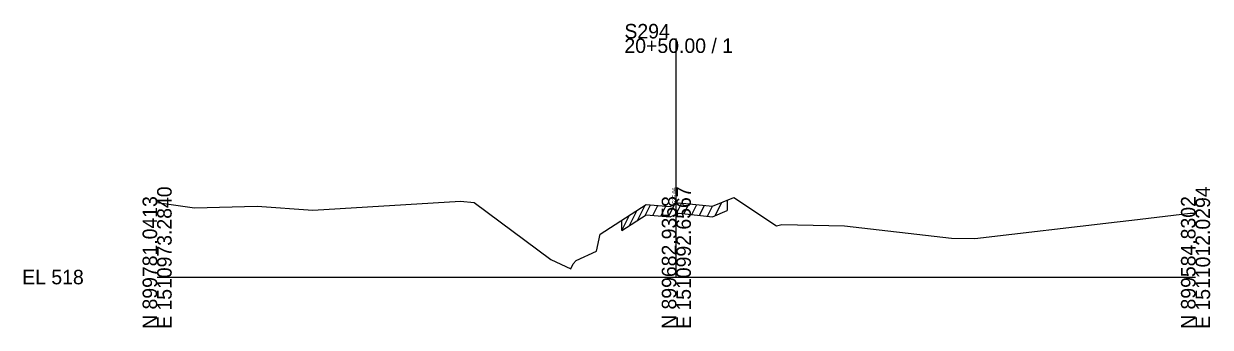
# Model space of a CAD drawing. Extents: x 974 to 2203, y -10 to 19041.
# Drawn here: x 1974.3 to 2202.8, y 990.3 to 1048.9 of the extents above; entities that cross this region are included whole.
import ezdxf

# ---------------------------------------------------------------- set-up
doc = ezdxf.new("R2010")
doc.units = 0
for name, color, linetype in [('RD_GPK_XS_Cell', 7, 'Continuous'), ('RD_XS_ExGround', 7, 'Continuous'), ('RD_XS_ExPaveRet', 7, 'Continuous'), ('RD_XS_TX_Elev_EX', 7, 'Continuous')]:
    doc.layers.add(name, color=color, linetype=linetype)

msp = doc.modelspace()

# ---------------------------------------------------------------- linework, layer by layer
at = {"layer": 'RD_GPK_XS_Cell'}
for p, q in [((2100, 1000), (2100, 1046.03)), ((2000, 1000), (2100, 1000)), ((2100, 1000), (2200, 1000))]:
    msp.add_line(p, q, dxfattribs=at)
at = {"layer": 'RD_XS_ExGround'}
msp.add_lwpolyline([(2000, 1014.37), (2007.18, 1013.33), (2019.27, 1013.68), (2030, 1012.91), (2058.46, 1014.65), (2061.07, 1014.39), (2075.82, 1003.39), (2079.71, 1001.6), (2080.13, 1002.56), (2080.71, 1003.17), (2084.63, 1004.97), (2085.35, 1008.28), (2094.18, 1014), (2098.79, 1013.62), (2100, 1014.11), (2100.57, 1014.35), (2106.98, 1013.65), (2111.06, 1015.34), (2119.3, 1009.89), (2120.3, 1010.13), (2132.37, 1009.87), (2152.97, 1007.5), (2157.51, 1007.44), (2184.93, 1010.66), (2187.74, 1011), (2198.98, 1012.32), (2200, 1012.35)], dxfattribs=at)
at = {"layer": 'RD_XS_ExPaveRet'}
for p, q in [((2109.78, 1014.81), (2109.78, 1012.81)), ((2090.99, 1009.94), (2092.47, 1012.9)), ((2092.49, 1010.91), (2093.97, 1013.87)), ((2093.99, 1011.88), (2095.02, 1013.93)), ((2095.49, 1011.89), (2096.45, 1013.82)), ((2096.99, 1011.77), (2097.95, 1013.69)), ((2098.49, 1011.65), (2099.66, 1013.97)), ((2099.99, 1012.11), (2101.08, 1014.29)), ((2101.49, 1012.25), (2102.44, 1014.14)), ((2102.99, 1012.08), (2103.94, 1013.98)), ((2104.49, 1011.92), (2105.44, 1013.82)), ((2105.99, 1011.76), (2106.94, 1013.66)), ((2106.98, 1011.65), (2109.78, 1012.81)), ((2107.49, 1011.86), (2108.76, 1014.39)), ((2089.49, 1008.97), (2094.18, 1012)), ((2089.49, 1008.97), (2090.97, 1011.92)), ((2089.49, 1008.97), (2089.49, 1010.97)), ((2094.18, 1012), (2098.79, 1011.62)), ((2098.79, 1011.62), (2100, 1012.11)), ((2100, 1012.11), (2100.57, 1012.35)), ((2100.57, 1012.35), (2106.98, 1011.65))]:
    msp.add_line(p, q, dxfattribs=at)

# ---------------------------------------------------------------- texts
at = {"layer": 'RD_GPK_XS_Cell'}
for s, p in [('S294', (2090, 1046.03)), ('20+50.00 / 1', (2090, 1043.23)), ('EL 518', (1974, 998.6))]:
    msp.add_text(s, height=2.8, dxfattribs=at).set_placement(p)
for s, p in [('E 1510973.2840', (2002.8, 990)), ('E 1510992.6567', (2102.8, 990)), ('E 1511012.0294', (2202.8, 990)), ('N 899781.0413', (2000, 990)), ('N 899682.9358', (2100, 990)), ('N 899584.8302', (2200, 990))]:
    msp.add_text(s, height=2.8, rotation=90, dxfattribs=at).set_placement(p)
at = {"layer": 'RD_XS_TX_Elev_EX'}
msp.add_text('525.06', height=0.75, rotation=90, dxfattribs=at).set_placement((2100, 1014.11))

doc.saveas('drawing.dxf')
